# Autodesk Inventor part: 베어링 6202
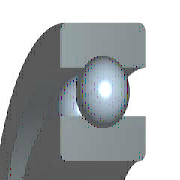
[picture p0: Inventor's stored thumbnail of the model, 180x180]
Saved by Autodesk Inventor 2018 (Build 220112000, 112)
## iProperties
IsCustomPart: 1
Created: 2015-12
Part Number: 베어링 6202
Material: 강철, 연강
Description: 깊은 그루브 볼 베어링
Document SubType Name: Modeling
Standard: KS B 2023
Designer: mdu
Standards Organization: KS
Language: ko-KR
Size Designation: 6202 - 15 x 35 x 11
Categories: <MemberInstance><Categories><Category DisplayName="샤프트 부품" InternalName="7f7aeb1f-a693-4053-b835-cee3144e0d98" Mnemonic="SHFT"><Category DisplayName="베어링" Inter
Density: 7.86 g/cm^3
Mass: 45.8724 g
Surface Area: 51.5584 cm^2
Volume: 5.83618 cm^3
Appearance: 노란색
Author: mdu
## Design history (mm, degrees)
sketch "스케치" dims "d0" = 5.2 (= -0.26 x WD + 0.26 x BD)
  geometry: L1 (2.9, 12.5)-(8.1, 12.5); L2 (5.5, 12.5)-(5.5, 9.9); L3 (5.5, 12.5)-(5.5, 15.1); L4 (3.568, 10.76)-(0, 10.76); L5 (0, 7.5)-(11, 7.5); L6 (3.568, 14.24)-(0, 14.24); L7 (0, 17.5)-(11, 17.5); L8 (11, 7.5)-(11, 10.76); L9 (7.432, 10.76)-(11, 10.76); L10 (7.432, 14.24)-(11, 14.24); L11 (11, 17.5)-(11, 14.24); L12 (-1.4, 0)-(8.4, 0) reference; L13 (0, -0.3)-(0, 5.3) reference
  constraints: 22 end point, 4 point on line, 2 collinear, 2 perpendicular, 2 symmetric about line, 1 midpoint, 1 parallel, 14 other
  dimensions: "d9" = 15 diameter of L5 L12 (= WD); "d11" = 35 diameter of L7 L12 (= BD); "d12" = 11 distance between parallel lines of L8 L13 (= KB); "d13" = 21.52 diameter of L9 L12 (= 0.326 x BD + 0.674 x WD)
revolve "본체" stored, may be unused: angle "d6" = 90 deg
revolve "볼" stored, may be unused: angle "d7" = 90 deg
pattern_circular "IDS_ARRAYBALL[SIMPL:T]" dims angle "d3" = 360 deg
body "Solid1"
fillet "모깎기1" dims "d1" = 0.6 (= KRS)
other parameters: "WD" = 15 [user parameter; used in 5 equation terms], "BD" = 35 [user parameter; used in 5 equation terms], "KB" = 11 [user parameter; used in 1 equation term], "KRS" = 0.6 [user parameter; used in 1 equation term], "d4" = 0, "d5" = 0, "d8" = 0, "d14" = 0, "d15" = 0, "BBA" = 0 [user parameter], "BC0" = 3750000 [user parameter], "BC" = 7800000 [user parameter], "BR" = 17.5 (= 0.5 x BD) [user parameter], "WR" = 7.5 (= 0.5 x WD) [user parameter]
